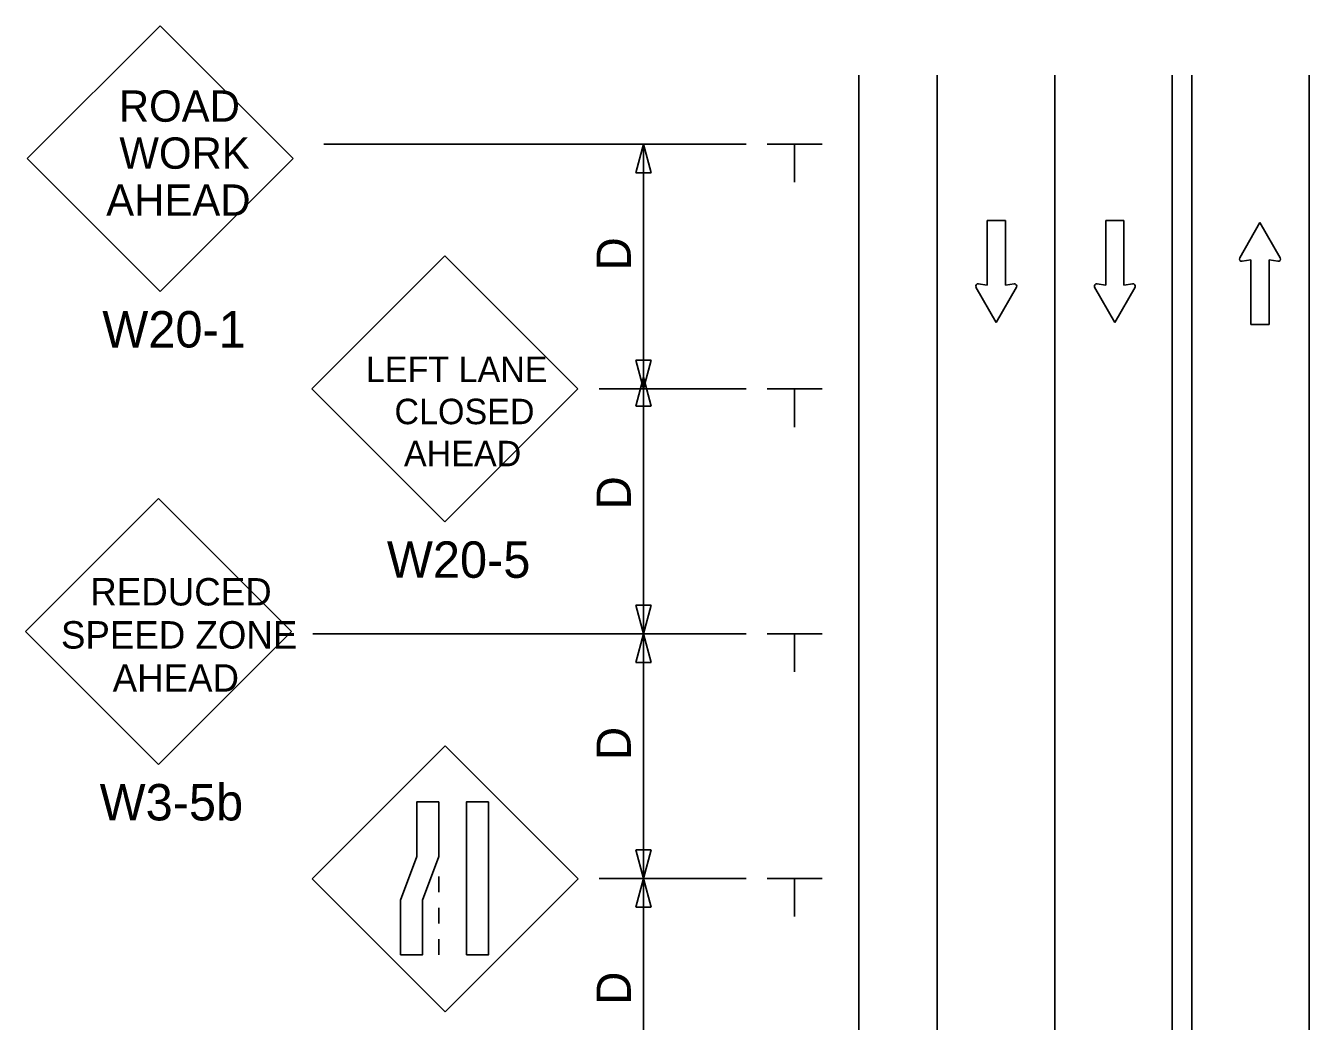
# Model space of a CAD drawing. Extents: x 16740 to 18475, y 5932 to 6927.
# Drawn here: x 16800 to 17062.1, y 6723.2 to 6926.6 of the extents above; entities that cross this region are included whole.
import ezdxf

# ---------------------------------------------------------------- set-up
doc = ezdxf.new("R2010")
doc.units = 0
for name, color, linetype in [('ALI_LEGAL_EX', 7, 'Continuous'), ('MT_SCRATCH_LEVEL_E', 7, 'Continuous'), ('PAVT_EDGE_EX', 7, 'Continuous'), ('TRAFFIC_SIGNS_PR', 7, 'Continuous'), ('TYPICAL_TEXT_DIMEN_PR', 7, 'Continuous')]:
    doc.layers.add(name, color=color, linetype=linetype)

msp = doc.modelspace()

# ---------------------------------------------------------------- linework, layer by layer
at = {"layer": 'ALI_LEGAL_EX'}
for p, q in [((17010.12, 6916.46), (17010.12, 6065.34)), ((17062.12, 6916.46), (17062.12, 6065.34))]:
    msp.add_line(p, q, dxfattribs=at)
for points in [[(17010.12, 6916.46), (17010.12, 6891.46)], [(17062.12, 6916.46), (17062.12, 6891.46)], [(17010.12, 6816.46), (17010.12, 6791.46)], [(17062.12, 6816.46), (17062.12, 6791.46)]]:
    msp.add_lwpolyline(points, dxfattribs=at)
at = {"layer": 'MT_SCRATCH_LEVEL_E'}
for p, q in [((17000.04, 6886.83), (16996.3, 6886.83)), ((16996.3, 6886.83), (16996.3, 6873.57)), ((17000.04, 6886.83), (16996.3, 6886.83)), ((16996.3, 6886.83), (16996.3, 6873.57)), ((17000.04, 6873.57), (17000.04, 6886.83)), ((17000.04, 6873.57), (17000.04, 6886.83)), ((17024.27, 6886.83), (17020.53, 6886.83)), ((17020.53, 6886.83), (17020.53, 6873.57)), ((17024.27, 6886.83), (17020.53, 6886.83)), ((17020.53, 6886.83), (17020.53, 6873.57)), ((17024.27, 6873.57), (17024.27, 6886.83)), ((17024.27, 6873.57), (17024.27, 6886.83)), ((17052.03, 6886.4), (17047.92, 6879.15)), ((17052.03, 6886.4), (17047.92, 6879.15)), ((17056.18, 6879.15), (17052.03, 6886.4)), ((17056.18, 6879.15), (17052.03, 6886.4)), ((17048.4, 6878.47), (17050.18, 6878.79)), ((17048.4, 6878.47), (17050.18, 6878.79)), ((17050.18, 6878.79), (17050.18, 6865.53)), ((17050.18, 6878.79), (17050.18, 6865.53)), ((17053.92, 6865.53), (17053.92, 6878.79)), ((17053.92, 6878.79), (17055.7, 6878.47)), ((17053.92, 6865.53), (17053.92, 6878.79)), ((17053.92, 6878.79), (17055.7, 6878.47)), ((16996.3, 6873.57), (16994.52, 6873.89)), ((16996.3, 6873.57), (16994.52, 6873.89)), ((17001.82, 6873.89), (17000.04, 6873.57)), ((17001.82, 6873.89), (17000.04, 6873.57)), ((17020.53, 6873.57), (17018.75, 6873.89)), ((17020.53, 6873.57), (17018.75, 6873.89)), ((17026.05, 6873.89), (17024.27, 6873.57)), ((17026.05, 6873.89), (17024.27, 6873.57)), ((16994.04, 6873.2), (16998.19, 6865.96)), ((16994.04, 6873.2), (16998.19, 6865.96)), ((16998.19, 6865.96), (17002.3, 6873.2)), ((16998.19, 6865.96), (17002.3, 6873.2)), ((17018.27, 6873.2), (17022.42, 6865.96)), ((17018.27, 6873.2), (17022.42, 6865.96)), ((17022.42, 6865.96), (17026.53, 6873.2)), ((17022.42, 6865.96), (17026.53, 6873.2)), ((17050.18, 6865.53), (17053.92, 6865.53)), ((17050.18, 6865.53), (17053.92, 6865.53))]:
    msp.add_line(p, q, dxfattribs=at)
for centre, start, end in [((17048.33, 6878.93), 150.4248, 279.9638), ((17048.33, 6878.93), 150.4248, 279.9638), ((17055.77, 6878.93), 260.0362, 29.7731), ((17055.77, 6878.93), 260.0362, 29.7731), ((16994.45, 6873.43), 80.0362, 209.7731), ((16994.45, 6873.43), 80.0362, 209.7731), ((17001.89, 6873.43), 330.4248, 99.9638), ((17001.89, 6873.43), 330.4248, 99.9638), ((17018.68, 6873.43), 80.0362, 209.7731), ((17018.68, 6873.43), 80.0362, 209.7731), ((17026.12, 6873.43), 330.4248, 99.9638), ((17026.12, 6873.43), 330.4248, 99.9638)]:
    msp.add_arc(centre, 0.463, start, end, dxfattribs=at)
at = {"layer": 'PAVT_EDGE_EX'}
for p, q in [((16970.12, 6916.46), (16970.12, 6065.34)), ((16986.12, 6916.46), (16986.12, 6065.34)), ((17034.12, 6916.46), (17034.12, 6547.86)), ((17038.12, 6916.46), (17038.12, 6547.86))]:
    msp.add_line(p, q, dxfattribs=at)
at = {"layer": 'TRAFFIC_SIGNS_PR'}
for p, q in [((16827.45, 6926.6), (16800.3, 6899.45)), ((16854.6, 6899.45), (16827.45, 6926.6)), ((16800.3, 6899.45), (16827.45, 6872.3)), ((16827.45, 6872.3), (16854.6, 6899.45)), ((16885.56, 6879.56), (16858.41, 6852.41)), ((16912.72, 6852.41), (16885.56, 6879.56)), ((16858.41, 6852.41), (16885.56, 6825.26)), ((16885.56, 6825.26), (16912.72, 6852.41)), ((16827.12, 6830.01), (16799.96, 6802.86)), ((16854.27, 6802.86), (16827.12, 6830.01)), ((16799.96, 6802.86), (16827.12, 6775.71)), ((16827.12, 6775.71), (16854.27, 6802.86)), ((16885.62, 6779.48), (16858.47, 6752.33)), ((16912.77, 6752.33), (16885.62, 6779.48)), ((16858.47, 6752.33), (16885.62, 6725.18)), ((16884.37, 6752.82), (16884.37, 6749.62)), ((16885.62, 6725.18), (16912.77, 6752.33)), ((16884.37, 6746.42), (16884.37, 6743.22)), ((16884.37, 6740.02), (16884.37, 6736.82))]:
    msp.add_line(p, q, dxfattribs=at)
for points in [[(16884.37, 6768.07), (16884.37, 6756.88), (16881.03, 6748), (16881.03, 6736.82), (16876.54, 6736.82), (16876.54, 6748), (16879.88, 6756.88), (16879.88, 6768.07)], [(16894.51, 6768.07), (16894.51, 6736.82), (16890.02, 6736.82), (16890.02, 6768.07)]]:
    msp.add_lwpolyline(points, close=True, dxfattribs=at)
at = {"layer": 'TYPICAL_TEXT_DIMEN_PR'}
for p, q in [((16947.12, 6902.4), (16860.88, 6902.4)), ((16924.55, 6896.54), (16926.12, 6902.4)), ((16926.12, 6902.4), (16926.12, 6852.4)), ((16926.12, 6902.4), (16927.69, 6896.54)), ((16951.37, 6902.4), (16962.62, 6902.4)), ((16956.99, 6902.4), (16956.99, 6894.62)), ((16926.12, 6896.54), (16924.55, 6896.54)), ((16927.69, 6896.54), (16926.12, 6896.54)), ((16926.12, 6852.4), (16924.55, 6858.26)), ((16924.55, 6858.26), (16926.12, 6858.26)), ((16926.12, 6858.26), (16927.69, 6858.26)), ((16927.69, 6858.26), (16926.12, 6852.4)), ((16924.55, 6848.91), (16926.12, 6854.78)), ((16926.12, 6854.78), (16926.12, 6802.4)), ((16926.12, 6854.78), (16927.69, 6848.91)), ((16947.12, 6852.4), (16917.06, 6852.4)), ((16951.37, 6852.4), (16962.62, 6852.4)), ((16956.99, 6852.4), (16956.99, 6844.62)), ((16926.12, 6848.91), (16924.55, 6848.91)), ((16927.69, 6848.91), (16926.12, 6848.91)), ((16926.12, 6802.4), (16924.55, 6808.26)), ((16924.55, 6808.26), (16926.12, 6808.26)), ((16926.12, 6808.26), (16927.69, 6808.26)), ((16927.69, 6808.26), (16926.12, 6802.4)), ((16947.12, 6802.4), (16858.6, 6802.4)), ((16924.55, 6796.54), (16926.12, 6802.4)), ((16926.12, 6802.4), (16926.12, 6752.4)), ((16926.12, 6802.4), (16927.69, 6796.54)), ((16951.37, 6802.4), (16962.62, 6802.4)), ((16956.99, 6802.4), (16956.99, 6794.62)), ((16926.12, 6796.54), (16924.55, 6796.54)), ((16927.69, 6796.54), (16926.12, 6796.54)), ((16926.12, 6752.4), (16924.55, 6758.26)), ((16924.55, 6758.26), (16926.12, 6758.26)), ((16926.12, 6758.26), (16927.69, 6758.26)), ((16927.69, 6758.26), (16926.12, 6752.4)), ((16947.12, 6752.4), (16917.06, 6752.4)), ((16924.55, 6746.54), (16926.12, 6752.4)), ((16926.12, 6752.4), (16927.69, 6746.54)), ((16926.12, 6752.4), (16926.12, 6702.4)), ((16951.37, 6752.4), (16962.62, 6752.4)), ((16956.99, 6752.4), (16956.99, 6744.62)), ((16926.12, 6746.54), (16924.55, 6746.54)), ((16927.69, 6746.54), (16926.12, 6746.54))]:
    msp.add_line(p, q, dxfattribs=at)

# ---------------------------------------------------------------- texts
at = {"layer": 'TRAFFIC_SIGNS_PR'}
for s, height, p in [('ROAD', 6.4, (16818.99, 6906.98)), ('WORK', 6.4, (16819.1, 6897.38)), ('AHEAD', 6.4, (16816.41, 6887.78)), ('W20-1', 7.44, (16815.62, 6860.86)), ('LEFT LANE', 5.2, (16869.45, 6853.81)), ('CLOSED', 5.2, (16875.28, 6845.2)), ('AHEAD', 5.2, (16877.22, 6836.61)), ('W20-5', 7.44, (16873.74, 6813.82)), ('REDUCED', 5.6, (16813.17, 6808.17)), ('SPEED ZONE', 5.6, (16807.17, 6799.37)), ('AHEAD', 5.6, (16817.73, 6790.57)), ('W3-5b', 7.44, (16815.07, 6764.27))]:
    msp.add_text(s, height=height, dxfattribs=at).set_placement(p)
at = {"layer": 'TYPICAL_TEXT_DIMEN_PR'}
for p in [(16923.56, 6876.62), (16923.56, 6827.81), (16923.56, 6776.62), (16923.56, 6726.62)]:
    msp.add_text('D', height=7, rotation=90, dxfattribs=at).set_placement(p)

doc.saveas('drawing.dxf')
